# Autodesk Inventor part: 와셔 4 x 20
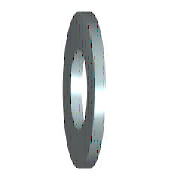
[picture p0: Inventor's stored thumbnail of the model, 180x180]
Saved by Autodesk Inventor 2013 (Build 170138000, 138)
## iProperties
IsCustomPart: 1
Created: 2012-02
Part Number: 와셔 4 x 20
Material: 강철, 연강
Description: 미터법 평면 와셔
Document SubType Name: Modeling
Standard: ANSI B18.22M
Designer: mduedu
Standard Revision: 1999
Standards Organization: ANSI
Language: ko-KR
Size Designation: 4 W
Categories: <MemberInstance><Categories><Category DisplayName="조임쇠" InternalName="e4da775c-781d-43d5-af7c-5136215cf5a6" Mnemonic="FSTN"><Category DisplayName="와셔" InternalN
Density: 1 g/cm^3
Author: mduedu
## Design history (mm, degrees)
sketch "스케치"
  geometry: C1 r 10 at (0, 0); C2 r 2.35 at (0, 0); 1 further point
  constraints: 2 centre point, 2 coincident
  dimensions: "d0" = 4.7 diameter of C2 (= SD1); "d1" = 20 diameter of C1 (= SD2)
extrude "본체" new body sketch "스케치" distance "d2" = 2.3 (= SD); taper "d3" = 0 deg
workaxis "Work Axis1"
workplane "Work Plane1"
body "Solid1"
other parameters: "SD1" = 4.7 [user parameter; used in 1 equation term], "SD2" = 20 [user parameter; used in 1 equation term], "SD" = 2.3 [user parameter; used in 1 equation term], "d4" = 0, "d5" = 0, "d6" = 0, "d7" = 0, "NND" = 4 [user parameter]
